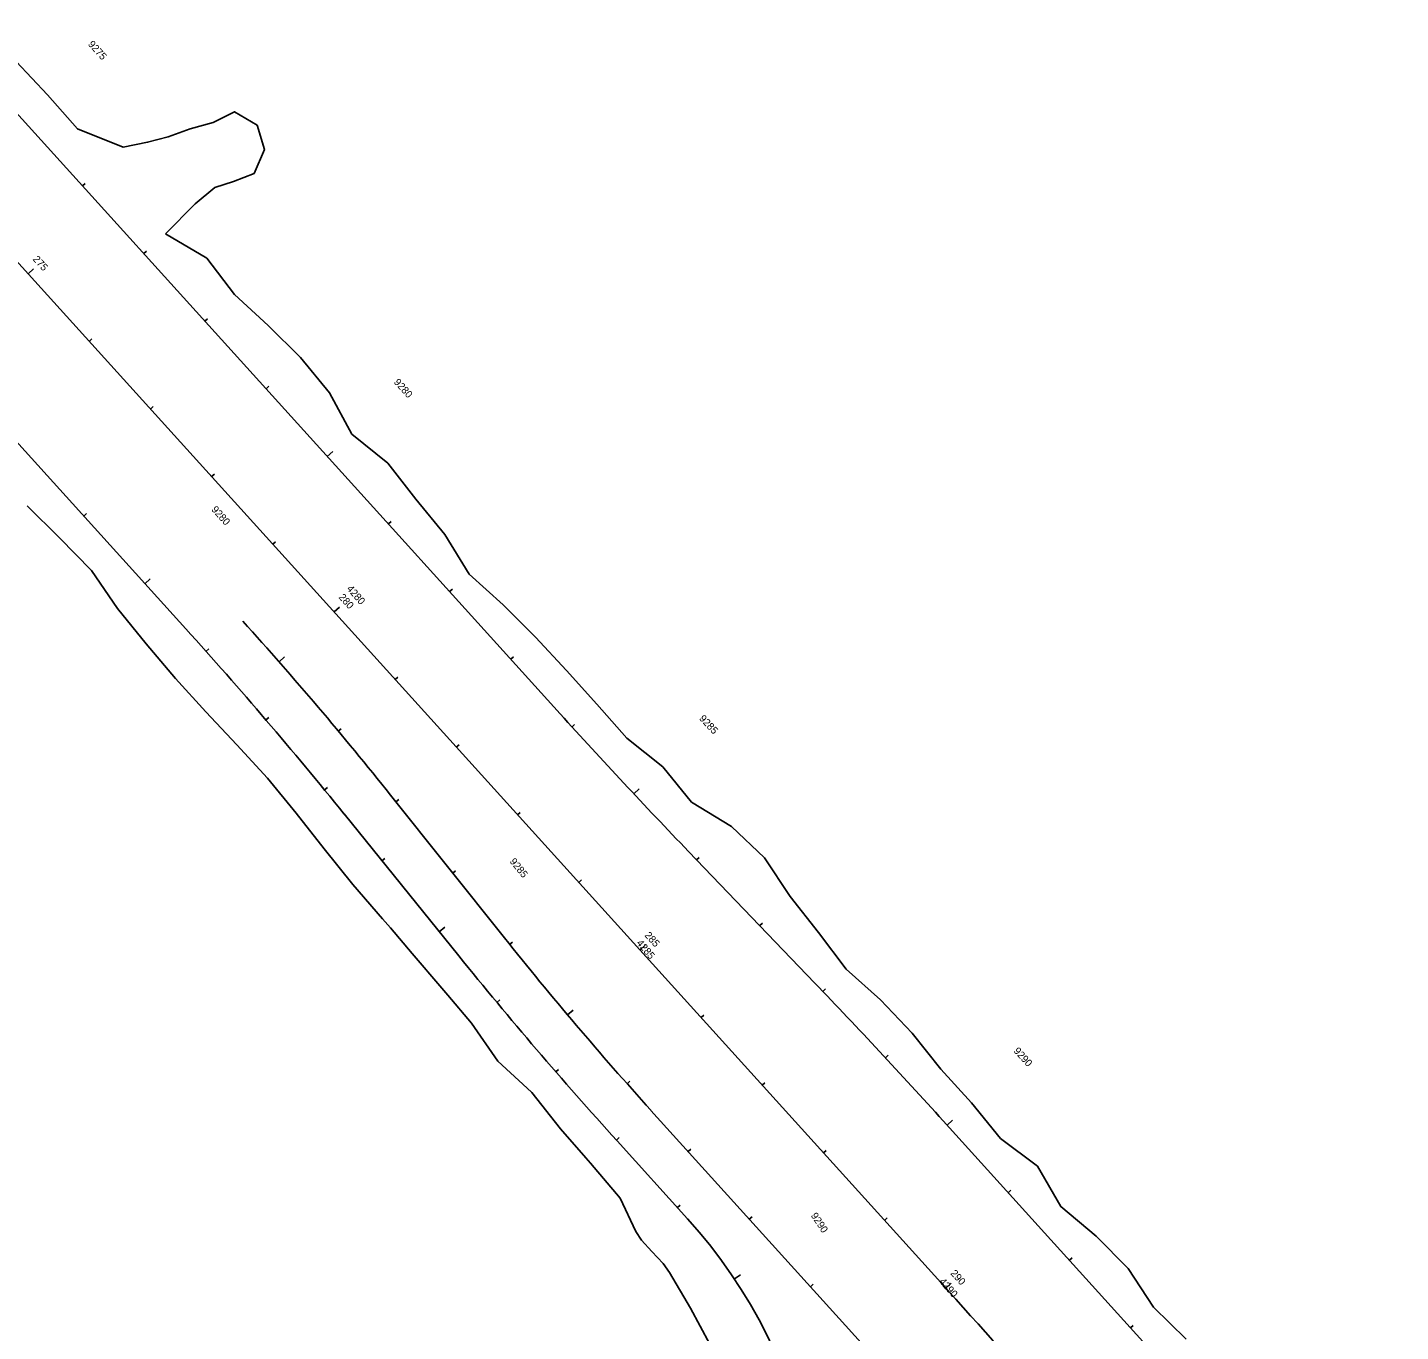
# Model space of a CAD drawing. Extents: x -5665 to 1997148, y 4 to 827579.
# Drawn here: x 1962331 to 1963836, y 805620 to 807051 of the extents above; entities that cross this region are included whole.
import ezdxf

# ---------------------------------------------------------------- set-up
doc = ezdxf.new("R2010")
doc.units = 0
for name, color, linetype in [('RD_HC_CL_Rel', 7, 'Continuous'), ('RD_HC_Data_Tic_Rel', 7, 'Continuous'), ('RD_HC_TX_Rel_Sta50', 7, 'Continuous'), ('RD_PD_CstnLmt', 7, 'Continuous')]:
    doc.layers.add(name, color=color, linetype=linetype)

msp = doc.modelspace()

# ---------------------------------------------------------------- linework, layer by layer
at = {"layer": 'RD_HC_CL_Rel'}
for p, q in [((1958130.1, 811424.7), (1963332.2, 805673.9)), ((1958645, 811017.9), (1962914.6, 806297.9)), ((1960806.2, 808268), (1962504.1, 806390.9)), ((1962728.8, 806208.5), (1962853.5, 806052.1)), ((1962677.8, 806187.9), (1962803.5, 806032.3)), ((1963055.5, 806146.7), (1963194, 806002.5)), ((1963014.2, 805862.8), (1963227.6, 805627)), ((1963334.8, 805851.3), (1963783, 805355.8)), ((1962977.2, 805829.3), (1963054.5, 805743.8))]:
    msp.add_line(p, q, dxfattribs=at)
for centre, radius, start, end in [((1959588.5, 803705.2), 4016, 38.5601, 42.1319), ((1958944.5, 803170.9), 4800, 38.9423, 42.1319), ((1968105.8, 810993.8), 7000, 222.13195, 223.82307), ((1965968.8, 808535.5), 3984, 218.5601, 222.1319), ((1966536.8, 809049.3), 4800, 218.9423, 222.1319), ((1958143.6, 801155.4), 7000, 42.13195, 43.82307), ((1962635.5, 805364.7), 565, 339.7688, 42.1319), ((1954834, 797986.6), 11459.2, 38.22442, 42.13195), ((1961373.6, 803949.9), 2500, 30.7484, 42.1319)]:
    msp.add_arc(centre, radius, start, end, dxfattribs=at)
at = {"layer": 'RD_HC_Data_Tic_Rel'}
for p, q in [((1962391, 806876.8), (1962394, 806879.5)), ((1962458.1, 806802.6), (1962461, 806805.3)), ((1962331.2, 806780.3), (1962337.2, 806785.7)), ((1962525.2, 806728.5), (1962528.1, 806731.1)), ((1962398.3, 806706.2), (1962401.3, 806708.9)), ((1962592.2, 806654.3), (1962595.2, 806657)), ((1962465.4, 806632), (1962468.4, 806634.7)), ((1962659.3, 806580.1), (1962665.3, 806585.5)), ((1962532.5, 806557.9), (1962535.5, 806560.5)), ((1962392.2, 806514.7), (1962395.2, 806517.4)), ((1962726.4, 806506), (1962729.4, 806508.7)), ((1962599.6, 806483.7), (1962602.5, 806486.4)), ((1962459.3, 806440.5), (1962465.2, 806445.9)), ((1962793.5, 806431.8), (1962796.5, 806434.5)), ((1962666.7, 806409.5), (1962672.6, 806414.9)), ((1962526.3, 806366.3), (1962529.3, 806369)), ((1962606.4, 806354.8), (1962612.4, 806360.1)), ((1962860.6, 806357.7), (1962863.5, 806360.3)), ((1962733.7, 806335.4), (1962736.7, 806338.1)), ((1962592.1, 806291), (1962595.1, 806293.6)), ((1962671.4, 806278.8), (1962674.5, 806281.4)), ((1962927.7, 806283.5), (1962930.6, 806286.2)), ((1962800.8, 806261.2), (1962803.8, 806263.9)), ((1962656.3, 806214.3), (1962659.4, 806216.9)), ((1962734.5, 806201.3), (1962737.7, 806203.8)), ((1962995.5, 806210), (1963001.3, 806215.5)), ((1962867.9, 806187.1), (1962870.9, 806189.7)), ((1962719.2, 806136.6), (1962722.3, 806139.1)), ((1963064.3, 806137.5), (1963067.2, 806140.3)), ((1962796.9, 806123.1), (1962800, 806125.6)), ((1962935, 806112.9), (1962938, 806115.6)), ((1963133.6, 806065.4), (1963136.5, 806068.1)), ((1962782.1, 806058.8), (1962788.3, 806063.9)), ((1962859.2, 806044.9), (1962862.3, 806047.4)), ((1963002.1, 806038.7), (1963008, 806044.1)), ((1963202.8, 805993.2), (1963205.7, 805996)), ((1962845.3, 805981.3), (1962848.4, 805983.9)), ((1962922.7, 805967.7), (1962928.8, 805972.8)), ((1963069.2, 805964.6), (1963072.1, 805967.3)), ((1963271.4, 805920.4), (1963274.4, 805923.2)), ((1962910, 805905.1), (1962913, 805907.7)), ((1962988.1, 805892), (1962991.1, 805894.7)), ((1963136.3, 805890.4), (1963139.2, 805893.1)), ((1963339, 805846.7), (1963344.9, 805852.1)), ((1962976.3, 805830.2), (1962979.3, 805832.9)), ((1963055, 805817.7), (1963058, 805820.4)), ((1963203.3, 805816.3), (1963206.3, 805818.9)), ((1963406.1, 805772.5), (1963409, 805775.2)), ((1963043.4, 805756.1), (1963046.3, 805758.8)), ((1963122.1, 805743.6), (1963125.1, 805746.2)), ((1963270.4, 805742.1), (1963273.4, 805744.8)), ((1963473.1, 805698.4), (1963476.1, 805701.1)), ((1963105.7, 805678), (1963112.4, 805682.5)), ((1963189.2, 805669.4), (1963192.2, 805672.1)), ((1963337.5, 805667.9), (1963343.4, 805673.3)), ((1963540.2, 805624.2), (1963543.2, 805626.9))]:
    msp.add_line(p, q, dxfattribs=at)
at = {"layer": 'RD_PD_CstnLmt'}
for points in [[(1962285.6, 807050.4), (1962318.2, 807013.2), (1962352.5, 806976.8), (1962385.5, 806939.3)], [(1962582.4, 806943.5), (1962557.4, 806958.2), (1962534.1, 806946.4), (1962509.1, 806939.5), (1962484.8, 806930.6), (1962462.2, 806924.7), (1962435.4, 806919.3), (1962385.5, 806939.3)], [(1962514.6, 806857.2), (1962536, 806875), (1962556.6, 806881.7), (1962579.1, 806890.4), (1962590.4, 806916.7), (1962582.4, 806943.5)], [(1962481.8, 806824.1), (1962514.6, 806857.2)], [(1962481.8, 806824.1), (1962527.1, 806797.6), (1962557.4, 806757.6), (1962594.6, 806723.8), (1962630.1, 806688.5), (1962661.7, 806649.7), (1962686.4, 806604.6), (1962725.7, 806572.8), (1962756.4, 806533.1), (1962788.3, 806494.5), (1962814.8, 806451.1), (1962852.1, 806417.4), (1962887.5, 806382), (1962921.5, 806345.3), (1962954.8, 806308.2), (1962987.8, 806271), (1963027.2, 806239.7), (1963058.6, 806201), (1963102.6, 806174.2), (1963138.8, 806139.7), (1963167, 806097.4), (1963197.9, 806057.8), (1963228.3, 806017.6), (1963265.9, 805983.9), (1963300.6, 805947.5), (1963332, 805908.1), (1963365.8, 805870.9), (1963397.4, 805832.1), (1963438.2, 805801.6), (1963463.6, 805757.2), (1963502.6, 805725), (1963537.6, 805689.2), (1963565.5, 805647.1), (1963601.1, 805611.9)], [(1962330.1, 806525.9), (1962365.8, 806490.8), (1962400.7, 806454.9), (1962429.2, 806413.3), (1962460.8, 806374.5), (1962492.9, 806336.5), (1962526.3, 806299.9), (1962560.1, 806263.6), (1962593.7, 806227.1), (1962625.1, 806188.7), (1962655.9, 806149.8), (1962687.2, 806110.7), (1962719.9, 806072.9), (1962728.5, 806062.9), (1962752.3, 806034.7), (1962785, 805996.7), (1962791.4, 805989.3), (1962817.5, 805958.3), (1962846.5, 805916.8), (1962883.3, 805882.7), (1962883.8, 805882.4), (1962915, 805842.7), (1962942.8, 805810.7), (1962945.4, 805807.7), (1962948.1, 805804.8), (1962980.4, 805766.5), (1962997.6, 805730), (1963003.8, 805720.3), (1963015.1, 805708.1), (1963015.1, 805708.1), (1963027.7, 805694.7), (1963034.7, 805685.1), (1963057.5, 805645.9), (1963078.9, 805606.5)]]:
    msp.add_lwpolyline(points, dxfattribs=at)

# ---------------------------------------------------------------- texts
at = {"layer": 'RD_HC_TX_Rel_Sta50'}
for s, rotation, p in [('9275', 312.1319, (1962396.4, 807031.8)), ('275', 312.1319, (1962335.9, 806796)), ('9280', 312.1319, (1962731.8, 806661.1)), ('9280', 312.1319, (1962531.7, 806521.4)), ('280', 312.1319, (1962671.3, 806425.2)), ('4280', 311.2824, (1962680, 806434.6)), ('9285', 313.1095, (1963066.6, 806292.1)), ('9285', 308.9423, (1962858.9, 806135.6)), ('285', 312.1319, (1963006.8, 806054.4)), ('4285', 310.1304, (1962997.9, 806046)), ('9290', 312.1319, (1963411.4, 805927.6)), ('9290', 303.676, (1963189.2, 805747.4)), ('4290', 311.1504, (1963329.8, 805674.7)), ('290', 312.092, (1963342.2, 805683.6))]:
    msp.add_text(s, height=8, rotation=rotation, dxfattribs=at).set_placement(p)

doc.saveas('drawing.dxf')
